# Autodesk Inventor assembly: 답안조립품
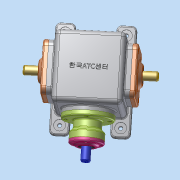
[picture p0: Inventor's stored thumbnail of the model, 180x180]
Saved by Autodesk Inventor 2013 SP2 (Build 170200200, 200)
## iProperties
Created: 2026-01
Part Number: 답안조립품
Document SubType Name: Assembly
Designer: a
Author: a
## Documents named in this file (16)
- C:\Users\a\Desktop\760103V1002\답안조립품.iam
- C:\Users\a\Desktop\760103V1002\본체.ipt
- C:\Users\a\Desktop\760103V1002\6각 구멍붙이 볼트 M4x10.ipt
- C:\Users\a\Desktop\760103V1002\6각 구멍붙이 볼트 M6x12.ipt
- C:\Users\a\Desktop\760103V1002\구동축.ipt
- C:\Users\a\Desktop\760103V1002\베벨 기어(구동).ipt
- C:\Users\a\Desktop\760103V1002\베벨 기어(종동).ipt
- C:\Users\a\Desktop\760103V1002\베어링 하우징.ipt
- C:\Users\a\Desktop\760103V1002\엔드캡.ipt
- C:\Users\a\Desktop\760103V1002\오일 실 20 35 8.ipt
- C:\Users\a\Desktop\760103V1002\종동축.ipt
- C:\Users\a\Desktop\760103V1002\측면 커버.ipt
- C:\Users\a\Desktop\760103V1002\칼라.ipt
- C:\Users\a\Desktop\760103V1002\테이퍼 롤러 베어링 30204K.ipt
- C:\Users\a\Desktop\760103V1002\평행 키 6x6x18.ipt
- C:\Users\a\Desktop\760103V1002\하우징 커버.ipt
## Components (19 placed, 4 different names)
1. 구동축:1 — 각도:4
2. 하우징 커버:1
3. 6각 구멍붙이 볼트 M6x12:1
4. 6각 구멍붙이 볼트 M6x12:2
5. 6각 구멍붙이 볼트 M6x12:3
6. 6각 구멍붙이 볼트 M6x12:4
7. 6각 구멍붙이 볼트 M6x12:5
8. 6각 구멍붙이 볼트 M6x12:6
9. 6각 구멍붙이 볼트 M6x12:7
10. 6각 구멍붙이 볼트 M6x12:8
11. 6각 구멍붙이 볼트 M6x12:9
12. 6각 구멍붙이 볼트 M6x12:10
13. 6각 구멍붙이 볼트 M6x12:11
14. 6각 구멍붙이 볼트 M6x12:12
15. 6각 구멍붙이 볼트 M6x12:13
16. 6각 구멍붙이 볼트 M4x10:1
17. 6각 구멍붙이 볼트 M4x10:2
18. 6각 구멍붙이 볼트 M4x10:3
19. 6각 구멍붙이 볼트 M4x10:4
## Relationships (1: Angle 1)
- 각도:4 [Angle]: 구동축:1
